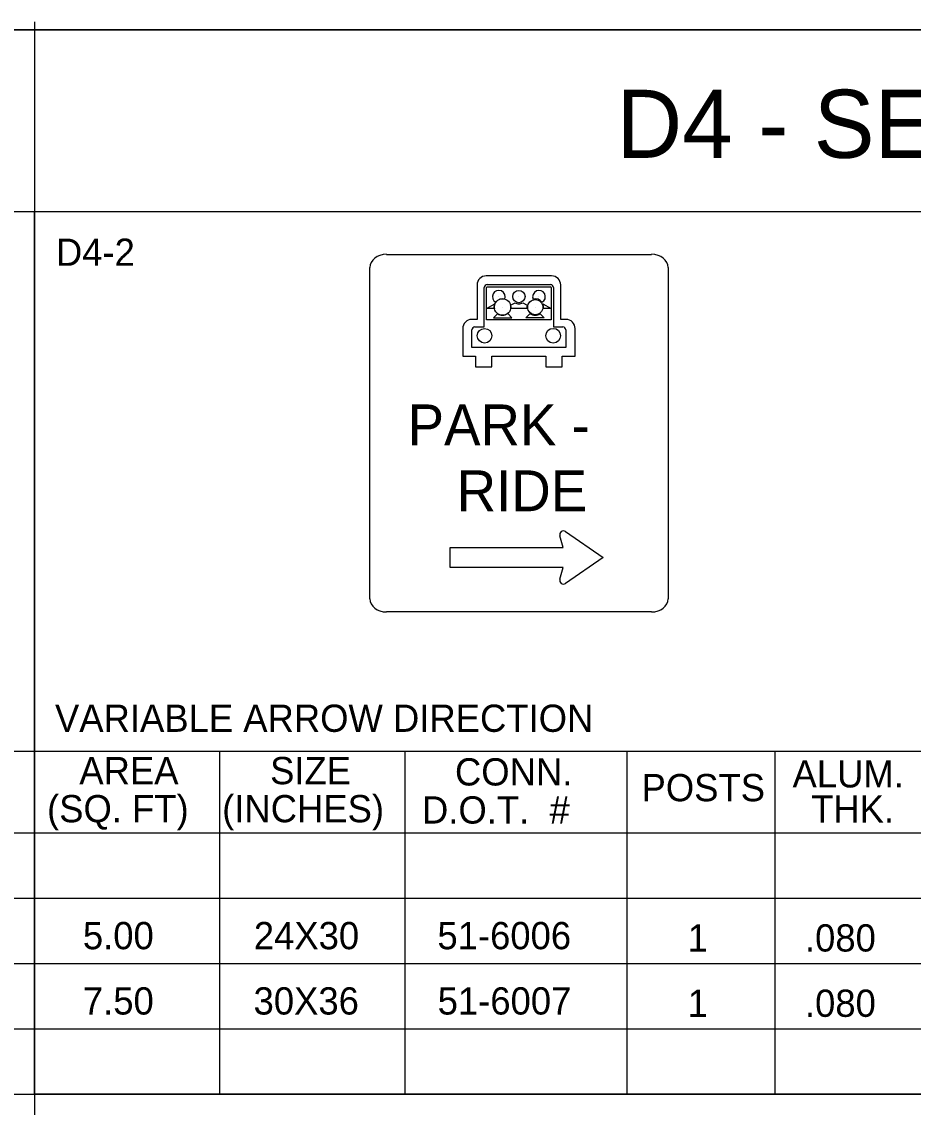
# Model space of a CAD drawing. Extents: x 0 to 2011, y -71 to 1183.
# Drawn here: x 213 to 317.8, y 702.5 to 830 of the extents above; entities that cross this region are included whole.
import ezdxf

# ---------------------------------------------------------------- set-up
doc = ezdxf.new("R2010")
doc.units = 0
for name, color, linetype in [('CT_Border_Perimeter_Shape', 7, 'Continuous'), ('CT_Construction', 7, 'Continuous'), ('Level 1', 7, 'Continuous'), ('Level 2', 7, 'Continuous'), ('Level 5', 7, 'Continuous')]:
    doc.layers.add(name, color=color, linetype=linetype)

msp = doc.modelspace()

# ---------------------------------------------------------------- linework, layer by layer
at = {"layer": 'CT_Border_Perimeter_Shape'}
msp.add_lwpolyline([(0, -0.97), (1270, -0.97), (1270, 829.03), (0, 829.03)], close=True, dxfattribs=at)
at = {"layer": 'CT_Construction'}
msp.add_lwpolyline([(0, 829.03), (1270, 829.03), (1270, 59.03), (0, 59.03)], close=True, dxfattribs=at)
at = {"layer": 'Level 1'}
for p, q in [((255.89, 802.68), (287.06, 802.68)), ((253.96, 762.22), (253.96, 801.14)), ((288.98, 801.14), (288.98, 762.22)), ((271.46, 800.15), (267.61, 800.15)), ((275.31, 800.15), (271.46, 800.15)), ((266.55, 799.09), (266.55, 795.03)), ((267.4, 794.15), (267.4, 798.79)), ((267.66, 794.97), (267.66, 798.79)), ((267.73, 799.12), (271.46, 799.12)), ((267.73, 798.85), (271.46, 798.85)), ((271.46, 799.12), (275.19, 799.12)), ((271.46, 798.85), (275.19, 798.85)), ((275.26, 798.79), (275.26, 794.97)), ((275.52, 798.79), (275.52, 794.15)), ((276.37, 795.03), (276.37, 799.09)), ((267.67, 796.31), (268.64, 796.85)), ((270.48, 796.73), (271.01, 796.99)), ((271.91, 796.99), (272.44, 796.73)), ((274.28, 796.85), (275.26, 796.31)), ((268.59, 796.31), (267.67, 796.31)), ((268.95, 795.71), (268.49, 795.23)), ((270.63, 795.23), (270.15, 795.72)), ((271.46, 796.31), (270.5, 796.31)), ((272.43, 796.31), (271.46, 796.31)), ((272.29, 795.23), (272.78, 795.72)), ((272.43, 796.31), (272.43, 796.31)), ((273.97, 795.71), (274.43, 795.23)), ((275.26, 796.31), (274.34, 796.31)), ((266.55, 795.03), (265.92, 795.03)), ((271.46, 794.97), (267.66, 794.97)), ((268.49, 795.23), (270.63, 795.23)), ((275.26, 794.97), (271.46, 794.97)), ((274.43, 795.23), (272.29, 795.23)), ((277, 795.03), (276.37, 795.03)), ((264.86, 793.97), (264.86, 790.73)), ((265.95, 791.75), (265.95, 793.82)), ((266.28, 794.15), (267.4, 794.15)), ((275.52, 794.15), (276.64, 794.15)), ((276.97, 793.82), (276.97, 791.75)), ((278.06, 790.73), (278.06, 793.97)), ((271.46, 791.75), (265.95, 791.75)), ((276.97, 791.75), (271.46, 791.75)), ((264.86, 790.73), (266.36, 790.73)), ((266.36, 790.73), (266.36, 789.47)), ((268.29, 789.47), (268.29, 790.73)), ((268.29, 790.73), (271.46, 790.73)), ((271.46, 790.73), (274.64, 790.73)), ((274.64, 790.73), (274.64, 789.47)), ((276.56, 789.47), (276.56, 790.73)), ((276.56, 790.73), (278.06, 790.73)), ((266.36, 789.47), (268.29, 789.47)), ((274.64, 789.47), (276.56, 789.47)), ((276.95, 770.12), (281.38, 767.08)), ((276.68, 768.25), (276.27, 769.63)), ((263.39, 765.9), (263.39, 768.25)), ((263.39, 768.25), (276.68, 768.25)), ((281.38, 767.08), (276.95, 764.03)), ((281.38, 767.08), (281.38, 767.08)), ((276.68, 765.91), (263.39, 765.9)), ((276.27, 764.53), (276.68, 765.91)), ((253.96, 762.22), (253.96, 762.22)), ((287.06, 760.68), (255.89, 760.68))]:
    msp.add_line(p, q, dxfattribs=at)
for centre, radius in [((271.46, 797.72), 0.724), ((269.54, 796.49), 0.971), ((273.39, 796.47), 0.89), ((267.43, 793.12), 0.855), ((275.49, 793.12), 0.861)]:
    msp.add_circle(centre, radius, dxfattribs=at)
for centre, radius, start, end in [((267.61, 799.09), 1.06, 89.9998, 180), ((275.31, 799.09), 1.06, 360, 90.0002), ((267.73, 798.79), 0.33, 90, 179.9999), ((267.73, 798.79), 0.066, 90, 179.9999), ((269.1, 797.7), 0.747, 338.1694, 241.5129), ((273.82, 797.7), 0.747, 298.4871, 201.8306), ((275.19, 798.79), 0.33, 0.0001, 90), ((275.19, 798.79), 0.066, 0.0001, 90), ((269.54, 796.49), 0.971, 157.7423, 190.3083), ((269.54, 796.49), 0.971, 74.7837, 144.8973), ((271.46, 797.72), 0.851, 237.9547, 269.8201), ((271.46, 797.72), 0.851, 270.1799, 302.0453), ((273.38, 796.49), 0.971, 35.1027, 105.2163), ((273.38, 796.49), 0.971, 349.6917, 22.2577), ((269.54, 796.49), 0.971, 232.6583, 308.4346), ((269.54, 796.49), 0.971, 349.691, 14.3149), ((273.38, 796.49), 0.971, 165.6851, 190.309), ((273.38, 796.49), 0.971, 231.5654, 307.3417), ((265.92, 793.97), 1.06, 89.9992, 180), ((277, 793.97), 1.06, 360, 90.0008), ((266.28, 793.82), 0.33, 89.9998, 180), ((276.64, 793.82), 0.33, 360, 90.0002), ((276.7, 769.75), 0.446, 55.5114, 196.6409), ((276.7, 764.4), 0.446, 163.3591, 304.4886)]:
    msp.add_arc(centre, radius, start, end, dxfattribs=at)
for centre, major_axis, start_param, end_param in [((255.89, 801.14), (-1.93, 0), 4.712389, 6.283185), ((287.06, 801.14), (1.93, 0), 0, 1.570796), ((255.89, 762.22), (-1.93, 0), 0, 1.570796), ((287.06, 762.22), (1.93, 0), 4.712389, 6.283185)]:
    msp.add_ellipse(centre, major_axis=major_axis, ratio=0.8, start_param=start_param, end_param=end_param, dxfattribs=at)
at = {"layer": 'Level 2'}
for p, q in [((269.1, 797.7), (269.1, 797.7)), ((271.46, 797.71), (271.46, 797.71)), ((271.46, 797.71), (271.46, 797.71)), ((273.82, 797.7), (273.82, 797.7)), ((269.54, 796.49), (269.54, 796.49)), ((273.38, 796.49), (273.38, 796.49)), ((109.8, 744.34), (214.55, 744.34)), ((214.55, 744.34), (319.3, 744.34)), ((236.3, 744.34), (236.3, 704.06)), ((258.05, 744.34), (258.05, 704.06)), ((284.15, 744.34), (284.15, 704.06)), ((301.55, 744.34), (301.55, 704.06)), ((109.8, 734.75), (214.55, 734.75)), ((214.55, 734.75), (319.3, 734.75)), ((109.8, 727.07), (214.55, 727.07)), ((214.55, 727.07), (319.3, 727.07)), ((109.8, 719.4), (214.55, 719.4)), ((214.55, 719.4), (319.3, 719.4)), ((109.8, 711.73), (214.55, 711.73)), ((214.55, 711.73), (319.3, 711.73))]:
    msp.add_line(p, q, dxfattribs=at)
for points in [[(214.55, 807.68), (109.8, 807.68), (109.8, 704.06), (214.55, 704.06)], [(319.3, 807.68), (214.55, 807.68), (214.55, 704.06), (319.3, 704.06)], [(319.3, 704.06), (214.55, 704.06), (214.55, 600.44), (319.3, 600.44)]]:
    msp.add_lwpolyline(points, close=True, dxfattribs=at)
at = {"layer": 'Level 5'}
for q in [(214.55, 704.06), (214.55, 496.81)]:
    msp.add_line((214.55, 830), q, dxfattribs=at)

# ---------------------------------------------------------------- texts
at = {"layer": 'Level 1'}
msp.add_text('D4 - SERIES', height=8, dxfattribs=at).set_placement((282.92, 814.01))
at = {"layer": 'Level 2'}
for s, height, p in [('D4-2', 3.2, (217.07, 801.33)), ('PARK -', 4.8, (258.39, 780.25)), ('RIDE', 4.8, (264.15, 772.51)), ('VARIABLE ARROW DIRECTION', 3.2, (216.96, 746.6)), ('AREA', 3.2, (219.82, 740.45)), ('SIZE', 3.2, (242.23, 740.45)), ('CONN.', 3.2, (263.95, 740.3)), ('ALUM.', 3.2, (303.61, 740.07)), ('POSTS', 3.2, (285.87, 738.45)), ('(SQ. FT)', 3.2, (216.03, 735.98)), ('(INCHES)', 3.2, (236.6, 735.98)), ('D.O.T.  #', 3.2, (260.08, 735.83)), ('THK.', 3.2, (305.79, 735.93))]:
    msp.add_text(s, height=height, dxfattribs=at).set_placement(p)
at = {"layer": 'Level 5'}
for s, p in [(' 5.00', (219.05, 721.07)), ('24X30', (240.32, 721.07)), ('51-6006', (261.89, 721.07)), ('1', (291.29, 720.8)), ('.080', (305.07, 720.8)), (' 7.50', (219.05, 713.4)), ('30X36', (240.29, 713.4)), ('51-6007', (261.92, 713.4)), ('1', (291.29, 713.13)), ('.080', (305.07, 713.13))]:
    msp.add_text(s, height=3.2, dxfattribs=at).set_placement(p)

doc.saveas('drawing.dxf')
